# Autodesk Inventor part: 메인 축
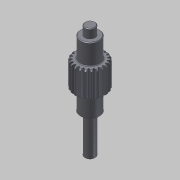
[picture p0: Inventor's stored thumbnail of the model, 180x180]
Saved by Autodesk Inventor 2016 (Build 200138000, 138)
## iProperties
Created: 2016-02
Part Number: 메인 축
Material: 강철, 연강
Document SubType Name: Modeling
Categories: <?xml version="1.0" encoding="UTF-16"?> <MemberInstance><Categories><FamilyTemplate><FamilyTemplateParameter ValueType="xs:double" Id="1" ObjectReferenceKey="da
Density: 7.86 g/cm^3
Appearance: 강철
CustomPartVersion: 1
Author: mdu
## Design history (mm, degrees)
sketch "Sketch1"
  geometry: C1 r 12 at (0, 0)
  constraints: 1 centre point
  dimensions: "d0" = 24 diameter of C1 (= da_da)
extrude "Extrusion1" new body sketch "Sketch1" distance "d1" = 20 (= da_b); taper "d2" = 0 deg
workplane "Work Plane2"
feature "피치 지름" dims "d4" = 10, "d5" = 0
workplane "Work Plane8"
workplane "Work Plane9"
chamfer "모따기1" distance "d49" = 1; stored, may be unused: second distance "d50" = 2, angle "d51" = 45 deg
sketch "스케치3"
  geometry: C1 r 7.5 at (0, 0); 1 further point
  constraints: 1 centre point, 1 coincident
  dimensions: "d52" = 15 diameter of C1
extrude "돌출2" join sketch "스케치3" distance "d53" = 16; taper "d54" = 0 deg
sketch "스케치4"
  geometry: C1 r 4 at (0, 0); 1 further point
  constraints: 1 centre point, 1 coincident
  dimensions: "d55" = 8 diameter of C1
extrude "돌출3" join sketch "스케치4" distance "d56" = 7; taper "d57" = 0 deg
sketch "스케치5"
  geometry: C1 r 7.5 at (0, 0) reference; C2 r 7.5 at (0, 0) reference; 1 further point
extrude "돌출4" join sketch "스케치5" distance "d62" = 16; taper "d63" = 0 deg
sketch "스케치6"
  geometry: C1 r 4 at (0, 0); 1 further point
  constraints: 1 centre point, 1 coincident
  dimensions: "d64" = 8 diameter of C1
extrude "돌출5" join sketch "스케치6" distance "d65" = 30; taper "d66" = 0 deg
chamfer "모따기2" distance "d58" = 0.5; stored, may be unused: second distance "d59" = 2, angle "d60" = 45 deg
fillet "모깎기1" dims "d61" = 0.5
feature "스퍼 기어" dims "d1" = 20 (= da_b), "d2" = 0, "d34" = 1.428 (computed from da_z), "da_b" = 20, "da_d" = 22, "da_aw" = 31, "da_da" = 24, "da_df" = 19.5, "da_dw" = 22, angle "da_beta" = 0 deg, "da_lefttooth" = 0, "da_righttooth" = 0
body "Solid1"
sketch "Sketch2"
  geometry: C1 r 12 at (0, 0) reference; C2 r 11 at (0, 0)
  constraints: 1 centre point, 1 coincident
  dimensions: "d3" = 22 diameter of C2 (= da_dw)
body "Srf1"
node "투영된 루프1"
other parameters: "d16" = 31 (= da_aw), "d17" = 0, "d39" = 0, "d41" = 0, "d43" = 31 (= da_aw), "d46" = 31 (= da_aw), "d47" = 0, "d48" = 0
